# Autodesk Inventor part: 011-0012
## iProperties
Created: 2007-02
Part Number: 011-0012
Material: Al Cu Mg 4
Document SubType Name: Modeling
Designer: GG5883
Project: GDB380
Description: Support mors mobile
Stock Number: 11-0012
Author: GG5883
Revision Number: 00
Title: SUPPORT MORS MOBILE
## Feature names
1. Appui sur glissière [Extrusion]
2. Face avant
3. Appui mors mobile [Extrusion]
4. usinage face arrière
5. passage colonne guidage [Hole]
6. passage axe de blocage [Hole]
7. perçage vis arrêt et d'arc boutement [Hole]
8. fixation mors mobile [Hole]
9. Réseau rectangulaire1 [Rectangular Pattern]
10. Corps dérivé1 [Tagging]
